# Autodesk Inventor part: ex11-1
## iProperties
Created: 2006-03
Part Number: ex11-1
Document SubType Name: Modeling
Designer: Elise Moss
Author: Elise Moss
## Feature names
1. Extrusion1
2. Extrusion2
3. Hole1
4. Fillet1
5. Hole2
6. Rectangular Pattern1
7. Fillet2
